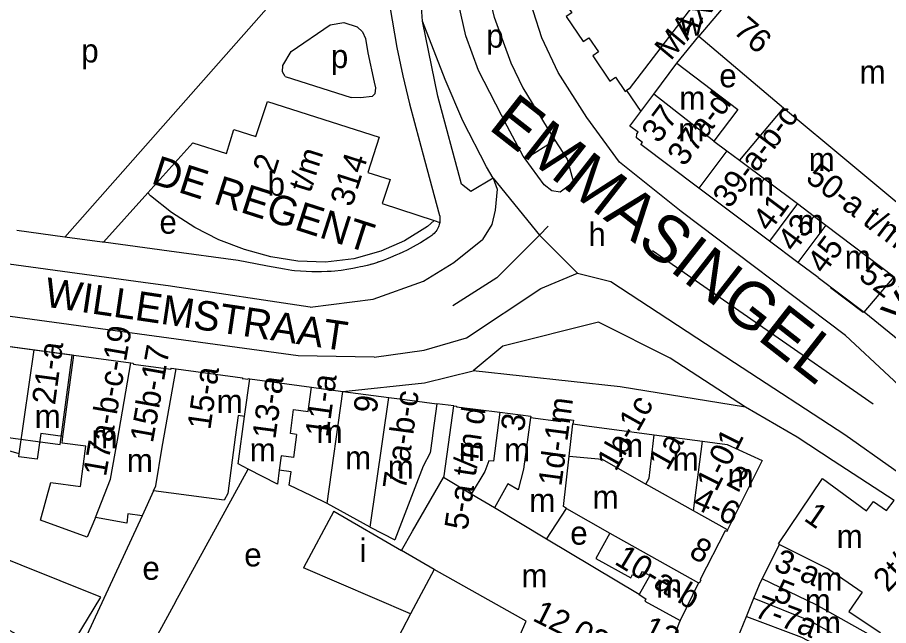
# Model space of a CAD drawing. Extents: x 160673 to 161924, y 382258 to 384145.
# Drawn here: x 161009.8 to 161158.4, y 383190.7 to 383294.4 of the extents above; entities that cross this region are included whole.
import ezdxf

# ---------------------------------------------------------------- set-up
doc = ezdxf.new("R2010")
doc.units = 0
for name, color, linetype in [('BLT_Basislijn', 7, 'Continuous'), ('BLT_Bebouwing', 7, 'Continuous'), ('BLT_Centroide', 7, 'Continuous'), ('BLT_Huisnummer', 7, 'Continuous'), ('BLT_Huisnummer_reeks', 7, 'Continuous'), ('BLT_Onderverdeling_panden', 7, 'Continuous'), ('BLT_Plantopo', 7, 'Continuous'), ('BLT_Straatnaam', 7, 'Continuous'), ('BLT_Straatnaam_hoofdweg', 7, 'Continuous'), ('BLT_Straatnaam_verkleind', 7, 'Continuous'), ('BLT_Vlakafsluiter', 7, 'Continuous')]:
    doc.layers.add(name, color=color, linetype=linetype)

msp = doc.modelspace()

# ---------------------------------------------------------------- linework, layer by layer
at = {"layer": 'BLT_Basislijn'}
for p, q in [((161078.89, 383293.73), (161078.29, 383303.11)), ((161056.96, 383301.15), (161017.91, 383256.94)), ((161081.52, 383280.94), (161078.89, 383293.73)), ((161096.4, 383270.28), (161101.51, 383273.44)), ((161032.06, 383264.45), (161024.5, 383256.04)), ((161080.93, 383259.78), (161081.85, 383259.44)), ((161017.91, 383256.94), (161009.72, 383258.07)), ((161081.55, 383258.46), (161081.42, 383258.23)), ((161100.33, 383258.78), (161098.89, 383257.28)), ((161118.17, 383254.61), (161155.79, 383228.48)), ((161072.78, 383253.16), (161072.19, 383252.95)), ((161072.19, 383252.95), (161070.53, 383252.38)), ((161148.51, 383248.32), (161154.07, 383244.12)), ((161163.13, 383236.85), (161154.26, 383244.11)), ((161084.23, 383228.12), (161081.35, 383228.48)), ((161036.77, 383194.74), (161049.18, 383217.36)), ((161159.38, 383211.99), (161148.97, 383218.79)), ((161036.77, 383194.74), (161030.43, 383183.09)), ((161076.84, 383192.65), (161071.59, 383182.56))]:
    msp.add_line(p, q, dxfattribs=at)
for points in [[(161151.06, 383240.13), (161123.05, 383261.29), (161112.51, 383269.69), (161106.93, 383277.35), (161102.07, 383284.97), (161099.24, 383290.91), (161096.4, 383299.86), (161095.76, 383303.36), (161094.72, 383311.45), (161094.7, 383319.2), (161095.15, 383324.24), (161096.06, 383329.18), (161097.56, 383334.74), (161125.59, 383422.21)], [(161096.4, 383270.28), (161096.1, 383270.7), (161093.35, 383275.84), (161088.47, 383285.32), (161086.29, 383291.26), (161085.09, 383296.55), (161084.57, 383301.96), (161084.59, 383305.94), (161084.86, 383309.16), (161085.95, 383310.07), (161087.94, 383310.01), (161088.44, 383309.59), (161088.56, 383307.94), (161089.04, 383304.03), (161089.64, 383300.37), (161091.11, 383294.43), (161093.99, 383286.64), (161096.03, 383282.39), (161100.16, 383275.54), (161101.51, 383273.44)], [(161067.03, 383298.15), (161073.33, 383296.26), (161074.52, 383289.29), (161075.54, 383284.45), (161076.69, 383279.64)], [(161055.46, 383284.34), (161055.03, 383285.11), (161055.08, 383286.2), (161056.53, 383288.58), (161063.18, 383293.12), (161065.47, 383293.53), (161067.76, 383292.8)], [(161090.94, 383266.95), (161089.83, 383268.93), (161085.81, 383276.76), (161082.78, 383283.79), (161078.89, 383293.73)], [(161067.76, 383292.8), (161068.65, 383291.92), (161069.19, 383290.82), (161069.61, 383288.35), (161070.66, 383283.35), (161070.89, 383282.39), (161070.76, 383281.36), (161070.32, 383280.89), (161068.31, 383280.69), (161066.76, 383280.72)], [(161055.46, 383284.34), (161066.76, 383280.72)], [(161090.94, 383266.95), (161087.14, 383264.72), (161085.57, 383265.93), (161081.52, 383280.94)], [(161076.69, 383279.64), (161079.26, 383270.12), (161081.83, 383260.61), (161081.85, 383260.53), (161081.87, 383260.34), (161081.89, 383260.17), (161081.89, 383259.99), (161081.88, 383259.71), (161081.85, 383259.44)], [(161101.51, 383273.44), (161103.58, 383270.22), (161104.67, 383266.3), (161102.38, 383264.57), (161100.96, 383264.79), (161099.64, 383265.81), (161096.4, 383270.28)], [(161090.94, 383266.95), (161091.66, 383265.11), (161091.3, 383261.54), (161090.73, 383259.06), (161089.15, 383256.53)], [(161081.85, 383259.44), (161081.78, 383259.1), (161081.7, 383258.83), (161081.63, 383258.66), (161081.55, 383258.46)], [(161059.75, 383244.98), (161036.26, 383248.5), (161035.95, 383248.53), (161031.27, 383249.2), (160966.6, 383257.99)], [(161081.42, 383258.23), (161081.33, 383258.09), (161081.2, 383257.9), (161081.08, 383257.74), (161080.91, 383257.56), (161080.69, 383257.36), (161080.51, 383257.21), (161080.33, 383257.08), (161080, 383256.87), (161078.56, 383255.97), (161077.81, 383255.54), (161076.79, 383254.99)], [(161024.5, 383256.04), (161024.27, 383256.07), (161017.91, 383256.94)], [(161047.48, 383252.91), (161035.68, 383254.52), (161024.5, 383256.04)], [(161059.75, 383244.98), (161070.5, 383246.34), (161079.1, 383249.41), (161084.28, 383252.61), (161089.15, 383256.53)], [(161098.89, 383257.28), (161091.58, 383249.97), (161084.09, 383245.2)], [(161076.79, 383254.99), (161076.27, 383254.71), (161075.55, 383254.36), (161074.95, 383254.07), (161074.38, 383253.82), (161073.46, 383253.43), (161072.78, 383253.16)], [(161057.09, 383251.18), (161056.61, 383251.25), (161055.38, 383251.43), (161053.42, 383251.81), (161052.47, 383251.98), (161050.45, 383252.38), (161047.48, 383252.91)], [(161070.53, 383252.38), (161069.47, 383252.1), (161068.71, 383251.91), (161068.33, 383251.83), (161067.81, 383251.71), (161067.03, 383251.55), (161065.99, 383251.37)], [(161070.24, 383252.32), (161070.04, 383252.26)], [(161071.41, 383252.68), (161071.04, 383252.56)], [(161063.96, 383251.13), (161063.36, 383251.08), (161062.66, 383251.03), (161061.71, 383250.99), (161060.86, 383250.99), (161060.02, 383250.99), (161059.04, 383251.03), (161058.11, 383251.09), (161057.09, 383251.18)], [(161065.99, 383251.37), (161065.39, 383251.29), (161065.01, 383251.24), (161063.96, 383251.13)], [(161070.69, 383236.42), (161079.18, 383237.63), (161086.44, 383239.72), (161099.11, 383248.16), (161105.33, 383250.78)], [(161105.33, 383250.78), (161111.05, 383249.36), (161132.16, 383235.51), (161150.93, 383223.25), (161167.67, 383211.41), (161190.11, 383189.36), (161231.21, 383144.85)], [(161070.69, 383236.42), (161057.69, 383236.66), (161001.88, 383244.31)], [(161134.02, 383227.94), (161121.18, 383236.28), (161108.94, 383242.41), (161092.61, 383238.33), (161087.58, 383234.14)], [(161151.06, 383240.13), (161165.98, 383226.24), (161194.65, 383197.92), (161222.81, 383169.35), (161244.86, 383146.49), (161270.16, 383120.77), (161279.96, 383109.14)], [(161065.31, 383230.61), (161079.26, 383232.08), (161087.58, 383234.14)], [(161134.02, 383227.94), (161112.61, 383231.39), (161087.58, 383234.14)], [(161148.97, 383218.79), (161142.81, 383222.82), (161134.02, 383227.94)], [(161031.09, 383209.4), (161019.81, 383185.12), (161018.27, 383182.14)]]:
    msp.add_lwpolyline(points, dxfattribs=at)
at = {"layer": 'BLT_Bebouwing'}
for p, q in [((161122.3, 383286.57), (161126.07, 383291.21)), ((161113.73, 383281.9), (161116.16, 383278.33)), ((161114.3, 383275.85), (161116.16, 383278.33)), ((161126.05, 383265.28), (161116.17, 383272.7)), ((161138.09, 383256.24), (161126.05, 383265.28)), ((161142.96, 383252.59), (161138.09, 383256.24)), ((161146.4, 383250.01), (161142.96, 383252.59)), ((161154.26, 383244.11), (161159.38, 383250.12)), ((161146.4, 383250.01), (161154.26, 383244.11)), ((161012.66, 383237.69), (161019.43, 383236.77)), ((161073.15, 383229.58), (161075.88, 383229.21)), ((161075.88, 383229.21), (161081.35, 383228.48)), ((161106.94, 383224.76), (161118.45, 383223.21)), ((161118.45, 383223.21), (161126.65, 383222.11)), ((161136.87, 383218.82), (161130.92, 383206.97)), ((161077.22, 383206.76), (161082.48, 383215.93)), ((161059.95, 383212.77), (161056.19, 383214.64)), ((161033.04, 383213.67), (161031.09, 383209.4)), ((161062.66, 383211.49), (161059.95, 383212.77)), ((161069.96, 383207.47), (161062.66, 383211.49)), ((161063.79, 383210.16), (161058.64, 383200.51)), ((161063.79, 383210.16), (161075.34, 383203.47)), ((161069.96, 383207.47), (161074.19, 383205.27)), ((161130.92, 383206.97), (161130.79, 383206.71)), ((161075.34, 383203.47), (161077.22, 383206.76)), ((161130.79, 383206.71), (161130.54, 383206.84)), ((161115.85, 383195.94), (161100.07, 383205.39)), ((161136.87, 383198.65), (161139.8, 383204.47)), ((161076.84, 383192.65), (161058.64, 383200.51)), ((161080.88, 383200.25), (161076.84, 383192.65)), ((161125.98, 383197.98), (161122.86, 383191.51)), ((161134.17, 383192.23), (161135.43, 383195.33)), ((161130.79, 383183.88), (161134.17, 383192.23))]:
    msp.add_line(p, q, dxfattribs=at)
for points in [[(161102.05, 383298.58), (161104.36, 383295.18), (161103.4, 383294.53), (161106.3, 383290.26), (161107.28, 383290.93), (161108.93, 383288.51), (161107.94, 383287.83), (161110.88, 383283.51), (161111.86, 383284.18), (161113.51, 383281.75), (161113.73, 383281.9)], [(161126.07, 383291.21), (161140.5, 383278.98)], [(161122.3, 383286.57), (161132.71, 383278.67), (161128.63, 383273.3)], [(161046.75, 383275.28), (161050.51, 383274.06), (161052.47, 383280.05), (161071.53, 383273.94), (161069.61, 383267.95), (161073.37, 383266.73), (161072.05, 383262.63), (161080.93, 383259.78)], [(161140.5, 383278.98), (161132.96, 383270.03)], [(161116.17, 383272.7), (161116.45, 383273.07), (161115.41, 383273.85), (161115.49, 383274.52), (161115.7, 383274.8), (161114.3, 383275.85)], [(161032.06, 383264.45), (161039.76, 383273.02), (161045.45, 383271.19), (161046.75, 383275.28)], [(161128.63, 383273.3), (161130.83, 383271.64)], [(161130.83, 383271.64), (161132.96, 383270.03)], [(161080.93, 383259.78), (161079.76, 383258.75), (161075.82, 383256.28), (161071.79, 383254.51), (161067.19, 383253.21), (161062.35, 383252.65), (161057.62, 383252.82), (161053.03, 383253.58), (161048.54, 383254.8), (161044.18, 383256.47), (161040.06, 383258.56), (161036.11, 383261.1), (161032.49, 383263.98), (161032.06, 383264.45)], [(161001.38, 383239.22), (161012.66, 383237.69)], [(161019.43, 383236.77), (161029.17, 383235.45)], [(161029.17, 383235.45), (161029.57, 383235.4), (161029.62, 383235.27)], [(161029.62, 383235.27), (161035.97, 383234.42), (161036.09, 383234.57), (161036.92, 383234.46)], [(161036.92, 383234.46), (161048.18, 383232.91), (161048.17, 383232.81), (161048.32, 383232.79)], [(161048.32, 383232.79), (161049.14, 383232.68), (161049.16, 383232.79), (161049.45, 383232.75)], [(161049.45, 383232.75), (161059.95, 383231.34)], [(161059.95, 383231.34), (161065.31, 383230.61)], [(161065.31, 383230.61), (161073.15, 383229.58)], [(161081.35, 383228.48), (161080.68, 383223.52), (161080.55, 383222.56)], [(161082.48, 383215.93), (161082.63, 383216.2), (161083.57, 383223.2), (161084.23, 383228.12)], [(161084.23, 383228.12), (161084.72, 383228.09), (161084.7, 383227.96), (161092.11, 383227.04)], [(161047.47, 383226.5), (161046.97, 383222.79), (161045.68, 383213.2), (161045.08, 383212.06), (161033.04, 383213.67)], [(161049.18, 383217.36), (161047.45, 383218.27), (161048.54, 383226.35)], [(161048.54, 383226.35), (161047.47, 383226.5)], [(161092.11, 383227.04), (161097.37, 383226.38), (161097.34, 383226.17)], [(161010.12, 383219.94), (161004.95, 383221.42), (161005.4, 383224.79), (161002.43, 383225.19), (161001.83, 383220.71), (161000, 383220.98), (160998.97, 383221.12)], [(161097.34, 383226.17), (161102.51, 383225.47), (161102.58, 383225.99), (161104.66, 383225.72), (161104.57, 383225.08)], [(161104.57, 383225.08), (161106.94, 383224.76)], [(161017.57, 383222.9), (161013.79, 383223.41), (161013.2, 383219.03), (161010.05, 383219.46), (161010.12, 383219.94)], [(161023.16, 383209.12), (161021.69, 383205.72), (161013.75, 383208.64), (161015.54, 383215.04), (161020.58, 383214.36), (161021.51, 383221.26), (161017.42, 383221.8), (161017.57, 383222.9)], [(161080.55, 383222.56), (161080.23, 383220.15), (161079.04, 383217.88), (161074.19, 383205.27)], [(161126.65, 383222.11), (161130.86, 383221.55), (161136.87, 383218.82)], [(161054.47, 383217.17), (161054.15, 383214.78), (161049.18, 383217.36)], [(161056.19, 383214.64), (161056.49, 383216.9), (161054.47, 383217.17)], [(161139.8, 383204.47), (161139.65, 383204.63), (161147.15, 383215.76)], [(161147.15, 383215.76), (161154.67, 383210.22), (161155.83, 383211.82), (161158.06, 383210.29), (161159.38, 383211.99)], [(161100.07, 383205.39), (161103.48, 383210.65)], [(161103.48, 383210.65), (161110.88, 383206.44)], [(161031.09, 383209.4), (161028.67, 383209.72), (161028.45, 383208.12), (161023.16, 383209.12)], [(161110.88, 383206.44), (161108.47, 383202.13), (161114.44, 383198.8), (161114.76, 383199.37), (161115.82, 383198.78), (161116.45, 383199.9), (161117.68, 383199.21), (161115.85, 383195.94)], [(161130.54, 383206.84), (161126.28, 383198.55), (161126.37, 383198.41), (161126.11, 383197.91), (161125.98, 383197.98)], [(161110.48, 383181.61), (161095.55, 383189.07), (161096.62, 383191.43), (161080.88, 383200.25)], [(161135.43, 383195.33), (161136.38, 383197.67), (161136.87, 383198.65)], [(161122.86, 383191.51), (161122.64, 383191.04), (161117.87, 383178.2)]]:
    msp.add_lwpolyline(points, dxfattribs=at)
at = {"layer": 'BLT_Onderverdeling_panden'}
for p, q in [((161118.37, 383281.28), (161122.3, 383286.57)), ((161116.16, 383278.33), (161118.37, 383281.28)), ((161128.63, 383273.3), (161118.37, 383281.28)), ((161147.91, 383272.82), (161165.89, 383257.77)), ((161130.83, 383271.64), (161126.05, 383265.28)), ((161132.96, 383270.03), (161142.87, 383262.63)), ((161142.87, 383262.63), (161138.09, 383256.24)), ((161142.87, 383262.63), (161147.71, 383258.97)), ((161147.71, 383258.97), (161142.96, 383252.59)), ((161147.71, 383258.97), (161159.38, 383250.12)), ((161010.12, 383219.94), (161012.66, 383237.69)), ((161017.57, 383222.9), (161019.43, 383236.77)), ((161048.54, 383226.35), (161049.45, 383232.75)), ((161062.66, 383211.49), (161065.31, 383230.61)), ((161069.96, 383207.47), (161073.15, 383229.58)), ((161103.94, 383219.54), (161104.57, 383225.08)), ((161125.13, 383210.23), (161126.65, 383222.11)), ((161087.24, 383213.08), (161082.48, 383215.93)), ((161125.13, 383210.23), (161116.98, 383214.81)), ((161091.18, 383210.72), (161087.24, 383213.08)), ((161100.07, 383205.39), (161091.18, 383210.72)), ((161130.92, 383206.97), (161125.13, 383210.23)), ((161110.88, 383206.44), (161125.98, 383197.98))]:
    msp.add_line(p, q, dxfattribs=at)
for points in [[(161131.65, 383305.12), (161114.16, 383282.19), (161113.73, 383281.9)], [(161135.61, 383302.5), (161126.07, 383291.21)], [(161140.5, 383278.98), (161147.91, 383272.82)], [(161023.16, 383209.12), (161025.7, 383215.65), (161026.88, 383222.26), (161029.17, 383235.45)], [(161033.04, 383213.67), (161033.4, 383214.48), (161034.52, 383221.12), (161036.92, 383234.46)], [(161057.4, 383223.25), (161056.38, 383223.43), (161056.9, 383227.49), (161059.43, 383227.17), (161059.95, 383231.34)], [(161092.11, 383227.04), (161091.04, 383218.69), (161090.23, 383218.75), (161089.57, 383216.93), (161087.24, 383213.08)], [(161097.34, 383226.17), (161096.14, 383217.36), (161095.22, 383213.83), (161093.45, 383214.82), (161091.18, 383210.72)], [(161057.4, 383223.25), (161056.88, 383219.33), (161054.79, 383219.61), (161054.47, 383217.17)], [(161116.98, 383214.81), (161117.55, 383215.79), (161118.45, 383223.21)], [(161103.48, 383210.65), (161102.95, 383210.96), (161103.94, 383219.54)], [(161103.94, 383219.54), (161109.56, 383219.05), (161116.98, 383214.81)], [(161139.8, 383204.47), (161148.22, 383200.28), (161153.89, 383196.39), (161151.66, 383193.08), (161157, 383189.47)], [(161080.88, 383200.25), (161075.34, 383203.47)], [(161157, 383189.47), (161156.39, 383188.42), (161146.04, 383194.19), (161136.87, 383198.65)], [(161115.85, 383195.94), (161117, 383195.25), (161116.82, 383194.82), (161122.86, 383191.51)], [(161135.43, 383195.33), (161145.02, 383191.5), (161155.76, 383185.47)], [(161134.17, 383192.23), (161143.54, 383188.71), (161152.49, 383183.98)]]:
    msp.add_lwpolyline(points, dxfattribs=at)
at = {"layer": 'BLT_Plantopo'}
for points in [[(161006.07, 383223.03), (161017.09, 383221.55), (161019.13, 383236.79), (161001.37, 383239.17), (160997.11, 383206.28), (161003.48, 383203.75)], [(161024.06, 383195.51), (161003.48, 383203.75), (160997.11, 383206.28), (160996.26, 383199.42), (160968.78, 383163.17), (160975.31, 383158.38), (161001.86, 383193.48), (161009.53, 383189.28), (160993.76, 383163.64), (161003.18, 383157.96), (161010.1, 383169.97), (161008.8, 383170.77), (161011.89, 383175.83), (161013.36, 383174.93), (161017.76, 383182.13), (161016.4, 383182.96)]]:
    msp.add_lwpolyline(points, close=True, dxfattribs=at)
at = {"layer": 'BLT_Vlakafsluiter'}
for p, q in [((161090.94, 383266.95), (161098.89, 383257.28)), ((161098.89, 383257.28), (161105.33, 383250.78))]:
    msp.add_line(p, q, dxfattribs=at)

# ---------------------------------------------------------------- texts
at = {"layer": 'BLT_Centroide'}
for s, p in [('w', (161122.91, 383291.27)), ('p', (161089.78, 383289.24)), ('p', (161020.7, 383286.72)), ('p', (161063.27, 383285.76)), ('m', (161153.46, 383283.11)), ('e', (161129.54, 383282.47)), ('m', (161122.72, 383278.66)), ('m', (161122.55, 383273.28)), ('m', (161144.79, 383268.19)), ('b', (161052.49, 383263.97)), ('m', (161134.41, 383264)), ('e', (161034.04, 383257.5)), ('m', (161142.91, 383257.62)), ('h', (161107.2, 383255.4)), ('m', (161150.93, 383251.53)), ('m', (161043.79, 383226.94)), ('m', (161012.75, 383224.38)), ('m', (161060.84, 383221.78)), ('m', (161022.45, 383220.92)), ('m', (161085.09, 383218.75)), ('m', (161112.1, 383219.41)), ('m', (161049.43, 383218.65)), ('m', (161065.71, 383217.3)), ('m', (161092.83, 383218.67)), ('m', (161028.47, 383216.83)), ('m', (161121.58, 383217.11)), ('m', (161072.98, 383215.71)), ('m', (161130.95, 383214.27)), ('m', (161097.12, 383210.05)), ('m', (161107.92, 383210.59)), ('e', (161104.11, 383204.46)), ('m', (161149.55, 383203.89)), ('i', (161068.17, 383201.5)), ('e', (161048.5, 383200.75)), ('e', (161031.13, 383198.47)), ('m', (161095.79, 383197.19)), ('m', (161146.09, 383196.64)), ('m', (161118.75, 383195.45)), ('m', (161144.11, 383192.93)), ('m', (161145.84, 383189.12))]:
    msp.add_text(s, height=4, dxfattribs=at).set_placement(p)
at = {"layer": 'BLT_Huisnummer'}
for s, rotation, p in [('43', 53.1049, (161142.32, 383254.19)), ('9', 82.3437, (161071.06, 383226.74)), ('3', 82.3424, (161096.19, 383223.63)), ('1a', 60.7445, (161120.71, 383216.91)), ('8', 330.7422, (161124.16, 383202.54)), ('5', 338.2367, (161138.56, 383195.03))]:
    msp.add_text(s, height=4, rotation=rotation, dxfattribs=at).set_placement(p)
at = {"layer": 'BLT_Huisnummer_reeks'}
for s, rotation, p in [('76', 319.5677, (161131.73, 383291.86)), ('37a-d', 53.1028, (161123.55, 383268.8)), ('37', 53.1268, (161119.17, 383272.74)), ('39-a-b-c', 53.1074, (161131.29, 383261.64)), ('2', 72.1733, (161053.65, 383267.44)), ('t/m', 72.1733, (161059.77, 383264.3)), ('314', 72.1733, (161066.86, 383261.92)), ('50-a t/m m', 322.8587, (161144.07, 383266.63)), ('41', 53.1789, (161138.1, 383257.64)), ('45', 53.3362, (161147.39, 383250.44)), ('52', 323.1137, (161153.1, 383249.92)), ('17a-b-c-19', 80.1226, (161024.91, 383215.95)), ('21-a', 82.3445, (161016.22, 383228.19)), ('15b-17', 79.8184, (161032.91, 383221.69)), ('15-a', 81.905, (161042.72, 383223.93)), ('13-a', 82.3401, (161053.81, 383222.34)), ('11-a', 82.1066, (161062.82, 383222.68)), ('7-a-b-c', 82.3437, (161076.06, 383213.69)), ('1d-1m', 82.3446, (161102.59, 383214.3)), ('1b-1c', 60.7451, (161111.89, 383216.79)), ('5-a t/m d', 81.4138, (161086.57, 383206.81)), ('1-01', 63.3669, (161129, 383213.35)), ('2', 332.8153, (161130.52, 383214.7)), ('4-6', 335.5409, (161124.79, 383210.85)), ('1', 325.3835, (161143.78, 383208.71)), ('2t/m2b', 45.9857, (161158.27, 383196.19)), ('10-a-b', 328.9635, (161111.47, 383201.26)), ('3-a', 338.2367, (161138.62, 383200.18)), ('7-7a', 339.4172, (161135.29, 383192.25)), ('12 02-04-06', 333.4426, (161097.49, 383191.61)), ('12', 333.4426, (161116.12, 383188.93))]:
    msp.add_text(s, height=4, rotation=rotation, dxfattribs=at).set_placement(p)
at = {"layer": 'BLT_Straatnaam'}
for s, rotation, p in [('VRIJSTRAAT', 49.9696, (161160.68, 383241.37)), ('DE REGENT', 342.1928, (161032.45, 383266.13)), ('WILLEMSTRAAT', 351.5537, (161014.25, 383245.11))]:
    msp.add_text(s, height=5, rotation=rotation, dxfattribs=at).set_placement(p)
at = {"layer": 'BLT_Straatnaam_hoofdweg'}
msp.add_text('EMMASINGEL', height=8, rotation=321.9511, dxfattribs=at).set_placement((161089.95, 383275.5))
at = {"layer": 'BLT_Straatnaam_verkleind'}
msp.add_text('MAXIMAHOF', height=4, rotation=50.1608, dxfattribs=at).set_placement((161121.24, 383286.88))

doc.saveas('drawing.dxf')
